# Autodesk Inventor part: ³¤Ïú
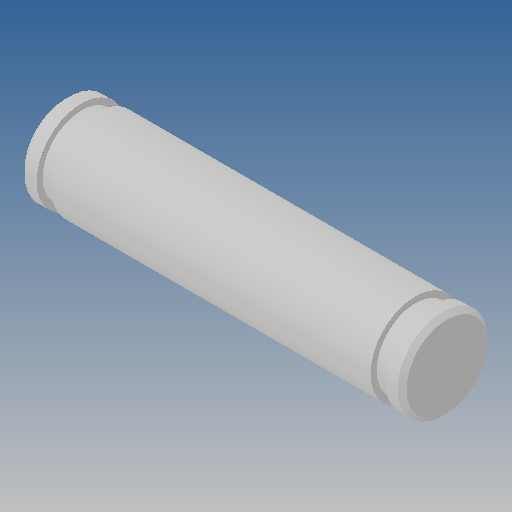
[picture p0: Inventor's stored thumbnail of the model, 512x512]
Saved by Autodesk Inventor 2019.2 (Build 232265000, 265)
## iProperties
Created: 2013-07
Part Number: ³¤Ïú
Material: Ogólny
Document SubType Name: Modeling
Designer: CADENGINEERING4
Density: 1 g/cm^3
Appearance: Domyślna
Author: CADENGINEERING4
Revision Number: ÈÎºÎ
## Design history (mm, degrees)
feature "Ðý×ª1"
node "Bryła1"
